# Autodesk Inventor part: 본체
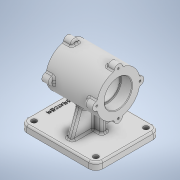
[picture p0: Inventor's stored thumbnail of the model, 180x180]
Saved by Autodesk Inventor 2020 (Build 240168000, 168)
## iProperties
Created: 2022-11
Part Number: 본체
Material: 일반
Document SubType Name: Modeling
Designer: owner
Density: 1 g/cm^3
Appearance: 기본값
Mass: 450.167 g
Surface Area: 796.807 cm^2
Volume: 450.167 cm^3
Author: owner
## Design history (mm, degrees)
sketch "스케치1"
  geometry: L1 (-65, -55)-(65, -55); L2 (65, -55)-(65, 55); L3 (65, 55)-(-65, 55); L4 (-65, 55)-(-65, -55); L5 (-65, -55)-(65, 55); L6 (65, -55)-(-65, 55); 1 further point
  constraints: 12 end point, 2 midpoint, 2 parallel, 1 horizontal, 1 perpendicular
  dimensions: "d0" = 130 distance of L3.end L2.end; "d1" = 110 distance of L2.end L1.end
extrude "돌출1" new body sketch "스케치1" distance "d2" = 12; taper "d3" = 0 deg
node "작업 평면1"
sketch "스케치3"
  geometry: L1 (110, 0)-(0, 0) reference; C1 r 37 at (55, 82); 2 further points
  constraints: 1 centre point, 1 midpoint, 1 vertical alignment
  dimensions: "d13" = 82 distance from line of L1 C1.centre; "d14" = 74 diameter of C1
extrude "돌출2" join sketch "스케치3" stored distance "d15" = 87; taper "d16" = 0 deg
sketch "스케치4"
  geometry: C1 r 37 at (0, 0) reference; A1 r 37 centre (0, 0) between (0, 37) and (-6.969, 36.338) reference; A2 r 7 centre (0, 37) between (6.969, 36.338) and (-6.969, 36.338); A3 r 7 centre (-37, 0) between (-36.338, 6.969) and (-36.338, -6.969); A4 r 7 centre (0, -37) between (-6.969, -36.338) and (6.969, -36.338); A5 r 7 centre (37, 0) between (36.338, -6.969) and (36.338, 6.969); 9 further points
  constraints: 11 point on circle, 4 centre point, 1 coincident, 1 vertical alignment, 17 other
  dimensions: "d17" = 14 diameter of A2; "d20" = 360 deg dimension on C1.centre A2.centre (derived)
extrude "돌출3" join sketch "스케치4" distance "d22" = 14; taper "d23" = 0 deg
sketch "스케치5"
  geometry: L1 (110, 0)-(0, 0) reference; L2 (0, 0)-(0, 12) reference; L3 (110, 12)-(0, 12) reference; L4 (110, 0)-(110, 12) reference; L5 (80.336, 55.036)-(96, 12); L6 (0, 12)-(110, 12) reference; L7 (29.664, 55.036)-(14, 12); A1 r 37 centre (55, 82) between (61.969, 45.662) and (91.338, 75.031) reference; A2 r 7 centre (55, 45) between (48.031, 45.662) and (61.969, 45.662) reference; A3 r 37 centre (55, 82) between (18.662, 75.031) and (48.031, 45.662) reference; A4 r 7 centre (18, 82) between (18.662, 88.969) and (18.662, 75.031) reference; A5 r 37 centre (55, 82) between (48.031, 118.338) and (18.662, 88.969) reference; A6 r 7 centre (55, 119) between (61.969, 118.338) and (48.031, 118.338) reference; A7 r 37 centre (55, 82) between (91.338, 88.969) and (61.969, 118.338) reference; A8 r 7 centre (92, 82) between (91.338, 75.031) and (91.338, 88.969) reference; A9 r 37 centre (55, 82) between (61.969, 45.662) and (91.338, 75.031) reference; A10 r 37 centre (55, 82) between (18.662, 75.031) and (48.031, 45.662) reference; A11 r 7 centre (55, 45) between (48.031, 45.662) and (61.969, 45.662) reference; A12 r 37 centre (55, 82) between (48.031, 45.662) and (61.969, 45.662) reference; 4 further points
  constraints: 4 end point, 2 point on circle, 2 point on line, 1 equal length
  dimensions: "d24" = 110 deg angle of L3 L5; "d25" = 110 deg angle of L3 L7; "d26" = 14 distance of L7.end L2.end
extrude "돌출4" join sketch "스케치5" stored distance "d27" = 10; taper "d28" = 0 deg
sketch "스케치6"
  geometry: L1 (-65, 0)-(65, 0) reference; L2 (65, 0)-(65, 12) reference; L3 (-65, 12)-(65, 12) reference; L4 (-65, 0)-(-65, 12) reference; L5 (0, 12)-(0, 55.036) reference; L6 (10, 55.036)-(10, 55.036) reference; L7 (10, 55.036)-(0, 55.036) reference; L8 (0, 55.036)-(0, 55.036) reference; L9 (0, 55.036)-(10, 55.036) reference; L10 (48.5, 45.662)-(34.5, 45.662) reference; L11 (34.5, 45.662)-(34.5, 45.662) reference; L12 (34.5, 45.662)-(48.5, 45.662) reference; L13 (48.5, 75.031)-(48.5, 45.662) reference; L14 (48.5, 75.031)-(34.5, 75.031) reference; L15 (34.5, 75.031)-(34.5, 88.969) reference; L16 (34.5, 88.969)-(48.5, 88.969) reference; L17 (48.5, 118.338)-(48.5, 88.969) reference; L18 (48.5, 118.338)-(34.5, 118.338) reference; L19 (34.5, 118.338)-(34.5, 118.338) reference; L20 (34.5, 118.338)-(48.5, 118.338) reference; L21 (48.5, 88.969)-(48.5, 118.338) reference; L22 (48.5, 88.969)-(34.5, 88.969) reference; L23 (34.5, 88.969)-(34.5, 75.031) reference; L24 (34.5, 75.031)-(48.5, 75.031) reference; L25 (48.5, 45.662)-(48.5, 75.031) reference; L26 (-38.5, 45.662)-(-24.5, 45.662) reference; L27 (-24.5, 45.662)-(-24.5, 45.662) reference; L28 (-24.5, 45.662)-(-38.5, 45.662) reference; L29 (-38.5, 75.031)-(-38.5, 45.662) reference; L30 (-38.5, 75.031)-(-24.5, 75.031) reference; L31 (-24.5, 75.031)-(-24.5, 88.969) reference; L32 (-24.5, 88.969)-(-38.5, 88.969) reference; L33 (-38.5, 118.338)-(-38.5, 88.969) reference; L34 (-38.5, 118.338)-(-24.5, 118.338) reference; L35 (-24.5, 118.338)-(-24.5, 118.338) reference; L36 (-24.5, 118.338)-(-38.5, 118.338) reference; L37 (-38.5, 88.969)-(-38.5, 118.338) reference; L38 (-38.5, 88.969)-(-24.5, 88.969) reference; L39 (-24.5, 88.969)-(-24.5, 75.031) reference; L40 (-24.5, 75.031)-(-38.5, 75.031) reference; L41 (-38.5, 45.662)-(-38.5, 75.031) reference; L42 (34.5, 45)-(-24.5, 45) reference; L43 (65, 12)-(-65, 12) reference; L44 (-15, 45)-(-15, 12); L45 (5, -25.2)-(5, 151.2) reference; 1 further point
  constraints: 2 end point, 2 point on line, 1 perpendicular
  dimensions: "d31" = 20 distance from line of L45 L44.end
feature "리브1" sketch "스케치6" dims "d32" = 1, "d33" = 10, "d34" = 0, "d35" = 0, "d36" = 1, "d37" = 1
sketch "스케치7"
  geometry: A1 r 7 centre (55, 45) between (48.031, 45.662) and (61.969, 45.662) reference; A2 r 37 centre (55, 82) between (61.969, 45.662) and (91.338, 75.031) reference; A3 r 7 centre (92, 82) between (91.338, 75.031) and (91.338, 88.969) reference; A4 r 37 centre (55, 82) between (91.338, 88.969) and (61.969, 118.338) reference; A5 r 7 centre (55, 119) between (61.969, 118.338) and (48.031, 118.338) reference; A6 r 37 centre (55, 82) between (48.031, 118.338) and (18.662, 88.969) reference; A7 r 7 centre (18, 82) between (18.662, 88.969) and (18.662, 75.031) reference; A8 r 37 centre (55, 82) between (18.662, 75.031) and (48.031, 45.662) reference; 1 further point
hole "구멍1" sketch "스케치7" at (55, 82) diameter "d38" = 42; stored, may be unused: countersink angle "d42" = 90 deg, drill point angle "d44" = 0 deg; dims "d39" = 8, "d40" = 47, "d41" = 19, "d43" = 87
sketch "스케치8"
  geometry: C1 r 21 at (-55, 82) reference; C2 r 23.5 at (-55, 82); 1 further point
  constraints: 1 centre point, 1 coincident
  dimensions: "d45" = 47 diameter of C2
extrude "돌출5" cut sketch "스케치8" distance "d46" = 19; taper "d47" = 0 deg
fillet "모깎기1" dims "d48" = 12
sketch "스케치10"
  geometry: A1 r 12 centre (-53, -43) between (-65, -43) and (-53, -55) reference; 2 further points
  constraints: 1 coincident
hole "구멍2" sketch "스케치10" at (-53, -43) diameter "d49" = 9; stored, may be unused: countersink angle "d53" = 90 deg, drill point angle "d55" = 0 deg; dims "d50" = 8, "d51" = 47, "d52" = 19, "d54" = 20
sketch "스케치12"
  geometry: L1 (55, 82)-(55, 132.865); C1 r 23.5 at (55, 82) reference; A1 r 37 centre (55, 82) between (61.969, 118.338) and (48.031, 118.338); A2 r 37 centre (55, 82) between (61.969, 118.338) and (48.031, 118.338) reference; 2 further points
  constraints: 2 end point, 1 centre point, 1 coincident, 1 point on circle, 1 point on line, 1 vertical
  dimensions: "d56" = 74 diameter of A1
hole "구멍3" sketch "스케치12" at (55, 119) diameter "d57" = 3.242; stored, may be unused: countersink angle "d61" = 90 deg, drill point angle "d63" = 118 deg; dims "d58" = 8, "d59" = 47, "d60" = 19, "d62" = 10
fillet "모깎기2" dims "d67" = 3
fillet "모깎기3" dims "d68" = 3
fillet "모깎기4" dims "d69" = 3
fillet "모깎기5" dims "d70" = 3
fillet "모깎기6" dims "d71" = 3
fillet "모깎기7" dims "d72" = 3
fillet "모깎기8" dims "d73" = 3
chamfer "모따기1" distance "d74" = 1; stored, may be unused: second distance "d75" = 2, angle "d76" = 45 deg
fillet "모깎기9" dims "d77" = 1
sketch "스케치13"
  geometry: 1 further point
sketch "스케치14"
  geometry: L1 (5, -77)-(5, 77) reference; L2 (-65, 43)-(-65, -43) reference; 3 further points
  constraints: 1 horizontal alignment, 1 midpoint, 1 other
  dimensions: "d78" = 58 distance from line of point (-53, 0) L1
feature "엠보싱1" sketch "스케치14" dims "d0" = 130, "d1" = 110, "d79" = 0.5, "d80" = 0
node "솔리드1"
mirror "미러1"
mirror "미러2"
mirror "미러3"
mirror "미러4"
pattern_circular "원형 패턴1" dims angle "d65" = 360 deg
mirror "미러5"
node "투영된 루프1"
node "투영된 루프2"
node "투영된 루프3"
node "투영된 루프4"
node "투영된 루프5"
node "작업 평면2"
node "투영된 루프6"
feature "A9D066F2-1C7D-4E18-AEED-F7BC21143FA4" dims "d38" = 42, "d39" = 8, "d40" = 47, "d41" = 19, "d42" = 90 deg, "d43" = 87, "d44" = 0
